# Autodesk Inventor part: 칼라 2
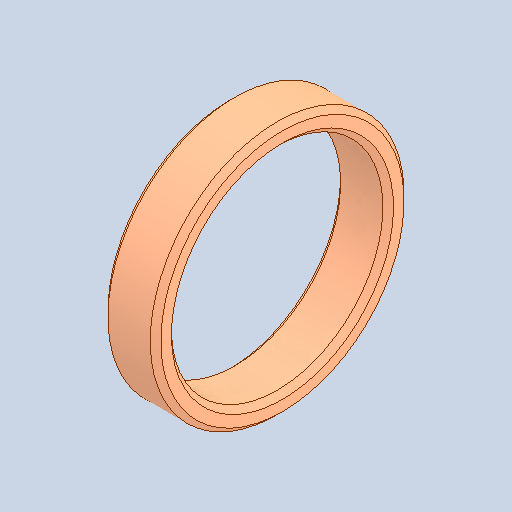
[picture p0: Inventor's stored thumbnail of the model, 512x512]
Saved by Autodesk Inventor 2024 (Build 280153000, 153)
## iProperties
Created: 2025-11
Part Number: 칼라 2
Material: 강철, 연강
Document SubType Name: Modeling
Designer: Edu07
Density: 7.85 g/cm^3
Appearance: 기본값
Author: jhkim
Sending System: Autodesk Inventor 2026
Preprocessor: ST-DEVELOPER v20.1
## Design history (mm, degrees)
node "칼라 21"
node "솔리드2"
node "솔리드1"
